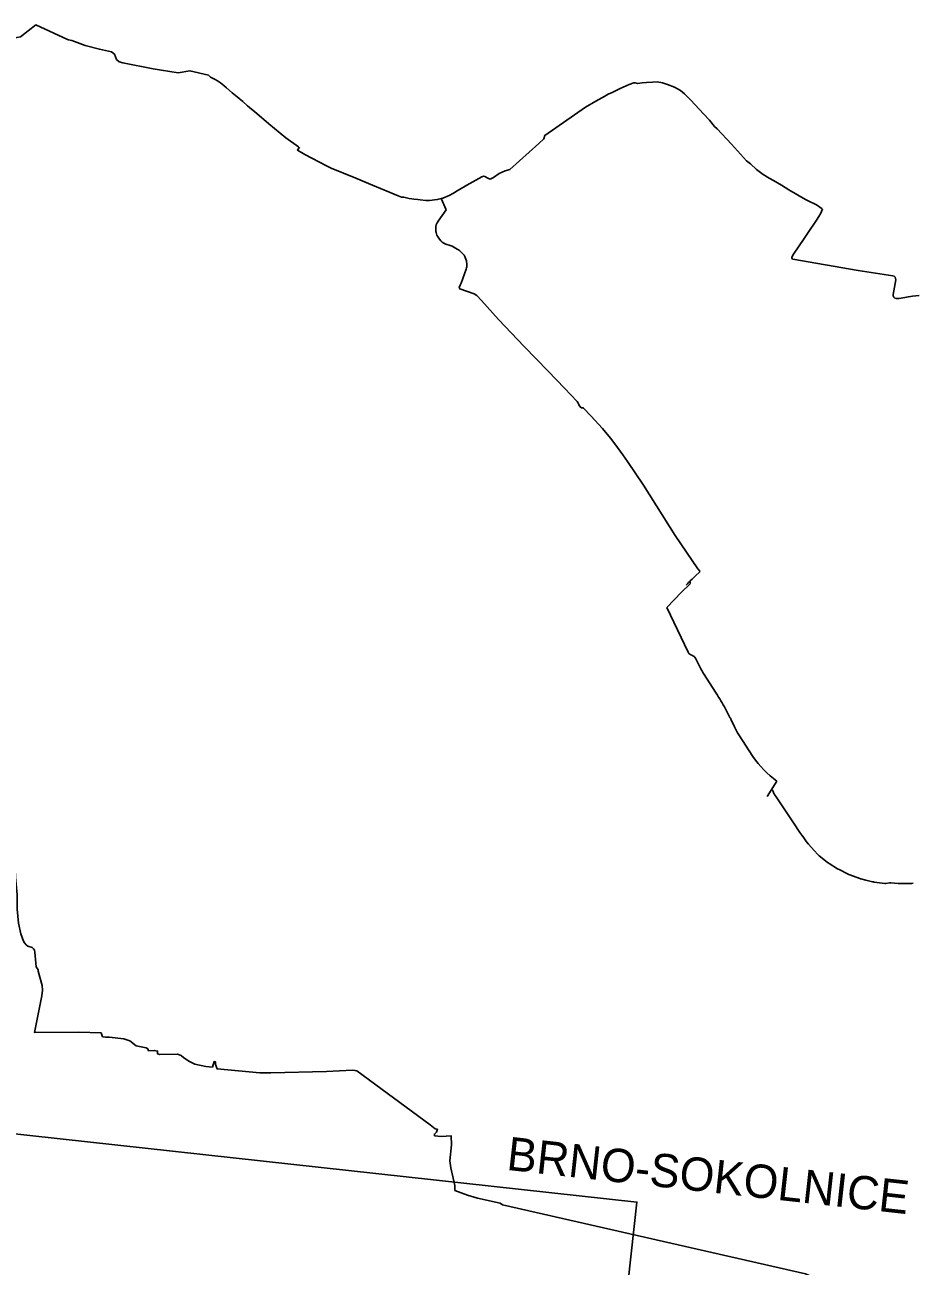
# Model space of a CAD drawing. Extents: x -678204 to -526855, y -1228851 to -1110393.
# Drawn here: x -596045 to -592047, y -1166903 to -1161319 of the extents above; entities that cross this region are included whole.
import ezdxf

# ---------------------------------------------------------------- set-up
doc = ezdxf.new("R2010")
doc.units = 0
for name, color, linetype in [('00_n_cyklo popisy ostatni', 7, 'Continuous'), ('00_n_cyklo provereni vedlejsi', 7, 'Continuous'), ('00_n_cyklo prujezdne podminecne rekreacni vedlejsi', 7, 'Continuous'), ('00_n_cyklo prujezdne rekreacni vedlejsi', 7, 'Continuous'), ('00_n_cyklo realizace rekreacni vedlejsi', 7, 'Continuous'), ('00_n_cyklo studie rekreacni vedlejsi', 7, 'Continuous'), ('00_n_cyklo trasovani rekreacni vedlejsi', 7, 'Continuous'), ('_HELP BIG', 7, 'Continuous')]:
    doc.layers.add(name, color=color, linetype=linetype)

msp = doc.modelspace()

# ---------------------------------------------------------------- linework, layer by layer
at = {"layer": '00_n_cyklo provereni vedlejsi'}
for p, q in [((-594063.9, -1162045.1), (-594055.8, -1162040.3)), ((-593007.5, -1163780.6), (-593026.2, -1163797.9)), ((-593053.4, -1163824.2), (-593051.1, -1163826.6)), ((-593050.2, -1163828.4), (-593050, -1163830.5))]:
    msp.add_line(p, q, dxfattribs=at)
for points in [[(-595994.8, -1161319.5), (-596063.8, -1161373.5), (-596097.6, -1161379.4), (-596197.5, -1161374), (-596330.9, -1161385.2)], [(-592456.3, -1162147.3), (-592482.8, -1162129.7), (-592519.5, -1162111.4), (-592532.2, -1162104.6), (-592606.1, -1162061.5), (-592639.6, -1162041.1), (-592675.4, -1162020.4), (-592695, -1162009.2), (-592722, -1161992.4), (-592752.3, -1161970.2), (-592779.3, -1161945.4), (-592797.4, -1161931), (-592864.9, -1161856), (-592929.3, -1161787.2), (-592940.6, -1161776.1), (-592963.2, -1161748.9), (-592991.1, -1161720.5), (-593048.4, -1161658.2), (-593076.4, -1161629.6), (-593094.6, -1161615.3), (-593121.4, -1161600.6), (-593153.5, -1161587.5), (-593175.4, -1161580.8), (-593199.7, -1161576.4), (-593219.6, -1161576.7), (-593247.8, -1161578.6), (-593266.2, -1161580.5), (-593288, -1161583.6)], [(-593441.7, -1161645.5), (-593435.4, -1161641), (-593419.5, -1161632), (-593401.3, -1161623.3), (-593365.4, -1161606.6), (-593325.4, -1161588.4), (-593304.6, -1161580.4), (-593298, -1161579.9), (-593288, -1161583.6)], [(-594055.8, -1162040.3), (-593987.5, -1162003.9), (-593981.1, -1162000.6), (-593974.3, -1162001.6), (-593958.9, -1162010.3), (-593950.5, -1162013.9), (-593935.3, -1162006.3), (-593910.1, -1161988.6), (-593882.5, -1161976.9), (-593862, -1161970.8), (-593731.7, -1161853.4), (-593708.8, -1161832.3), (-593704.2, -1161817), (-593521.4, -1161690.6), (-593476, -1161662.2), (-593435.4, -1161641)], [(-594099.4, -1162066), (-594115.3, -1162076.6), (-594134.5, -1162086.6), (-594164.4, -1162098.5), (-594171, -1162100.3)], [(-594099.4, -1162066), (-594063.9, -1162045.1)], [(-594364.4, -1162089.3), (-594349.9, -1162095), (-594344, -1162094.8), (-594338.7, -1162094.9), (-594326.8, -1162098), (-594314.5, -1162101), (-594303.1, -1162102.7), (-594294.3, -1162103.5), (-594276.8, -1162105.1), (-594265.6, -1162107.2), (-594240.5, -1162109.1)], [(-594171, -1162100.3), (-594189.1, -1162105.3), (-594223.1, -1162109.4), (-594240.5, -1162109.1)], [(-594149.4, -1162151.3), (-594170.9, -1162100.2)], [(-592593.2, -1162365.5), (-592590.6, -1162359.3), (-592585.7, -1162350.6), (-592560.5, -1162313.7), (-592541.1, -1162285.1), (-592522.7, -1162257.7), (-592482.7, -1162198.7), (-592471.6, -1162181.8), (-592461.7, -1162163.3), (-592455.6, -1162147.6)], [(-592588.7, -1162373.7), (-592294.7, -1162424.4), (-592138.6, -1162448.7)], [(-592126.1, -1162466), (-592137, -1162532.7)], [(-593005.2, -1163778.8), (-593016.6, -1163766.3), (-593118.8, -1163616.7), (-593260.7, -1163390.5), (-593332.9, -1163283.7), (-593354.5, -1163253.2), (-593390.5, -1163204.2), (-593409.6, -1163179.2), (-593445.8, -1163135.6), (-593497.8, -1163078.1), (-593531.1, -1163044.1), (-593534.3, -1163042.3), (-593537.1, -1163041.8), (-593540.6, -1163042.5), (-593550.9, -1163032.2), (-593552, -1163028), (-593554.2, -1163021.5), (-593559.4, -1163014.6), (-593616.3, -1162953.6), (-593690.3, -1162877.3), (-593797.3, -1162766), (-593912.9, -1162644.5), (-593989.9, -1162559.1), (-594010.6, -1162537.5), (-594023.4, -1162530), (-594087.2, -1162506.6), (-594089.6, -1162501.7), (-594085.2, -1162490.6), (-594081.1, -1162481)], [(-592123.2, -1162550.1), (-592114.2, -1162550.6)], [(-593051.3, -1163834.3), (-593089.4, -1163870.9), (-593156.3, -1163940.6)]]:
    msp.add_lwpolyline(points, dxfattribs=at)
for centre, radius, start, end in [((-592587.6, -1162367.8), 6, 157.2978, 260.2148), ((-592140.9, -1162463.6), 15, 350.7572, 81.145), ((-592122.2, -1162535.1), 15, 170.7572, 266.267), ((-592113.2, -1162535.7), 15, 266.267, 280.5096), ((-592347, -1164529.2), 998, 132.8816, 136.2737), ((-593054.4, -1163831), 4.5, 313.8822, 6.511), ((-593053.2, -1163828.7), 3, 6.511, 45.0583)]:
    msp.add_arc(centre, radius, start, end, dxfattribs=at)
at = {"layer": '00_n_cyklo prujezdne podminecne rekreacni vedlejsi'}
for points in [[(-595847.9, -1161386.6), (-595852.1, -1161385), (-595994.8, -1161319.5)], [(-594364.4, -1162089.3), (-594479.4, -1162040.8), (-594555.3, -1162008.9), (-594665.9, -1161964.9), (-594686.9, -1161954.1), (-594785.3, -1161902.7), (-594818.2, -1161882.6), (-594809.1, -1161870.1)]]:
    msp.add_lwpolyline(points, dxfattribs=at)
at = {"layer": '00_n_cyklo prujezdne rekreacni vedlejsi'}
for p, q in [((-593156.3, -1163940.6), (-593059.9, -1164142)), ((-593026.7, -1164168.6), (-593005.9, -1164210.1)), ((-592990.5, -1164237.1), (-592933.7, -1164325.7)), ((-592873.2, -1164432.5), (-592892, -1164397)), ((-592866.7, -1164445.5), (-592852, -1164476.9)), ((-592832, -1164512.7), (-592768.1, -1164611))]:
    msp.add_line(p, q, dxfattribs=at)
for points in [[(-595218.8, -1161546.6), (-595301.4, -1161526.2), (-595354.8, -1161534.7), (-595466.5, -1161518.1), (-595603, -1161490.7), (-595620.3, -1161486.7), (-595631.6, -1161474.8), (-595640.8, -1161451.6), (-595655.2, -1161441.2), (-595708.8, -1161429), (-595772.4, -1161413.2), (-595832.8, -1161389.7), (-595847.9, -1161386.6)], [(-595218.8, -1161546.6), (-595209, -1161555.4), (-595188.5, -1161565.9), (-595177.3, -1161572.1), (-595163.8, -1161581.1), (-595149.8, -1161591.8), (-595137.5, -1161602.7), (-595111.2, -1161625), (-595088.5, -1161644), (-595063.7, -1161664.5), (-595042.3, -1161683.2), (-595024.4, -1161698.2), (-595011.6, -1161709.3), (-594946.8, -1161764.7), (-594895.6, -1161807.5), (-594870.8, -1161827.3), (-594812.9, -1161867.8)], [(-594185, -1162203.4), (-594149.4, -1162151.3)], [(-594194.5, -1162248.5), (-594195.8, -1162235.4)], [(-594178.5, -1162284.1), (-594187.2, -1162270)], [(-594130.8, -1162311.5), (-594150.5, -1162305.6)], [(-594098.6, -1162328.2), (-594121, -1162315.7)], [(-594076, -1162346.9), (-594089.4, -1162334.8)], [(-594056.1, -1162397.4), (-594057.2, -1162381.6), (-594062.6, -1162366.8)], [(-594081.1, -1162481), (-594058.9, -1162418)]]:
    msp.add_lwpolyline(points, dxfattribs=at)
for centre, radius, start, end in [((-594146, -1162234.3), 49.8, 141.6362, 181.2596), ((-594144.7, -1162243.7), 50, 185.5177, 211.7691), ((-594136, -1162257.7), 50, 211.7691, 253.167), ((-594145.3, -1162359.4), 50, 60.8479, 73.167), ((-594123, -1162371.9), 50, 47.8163, 60.8479), ((-594109.6, -1162384), 50, 20.0691, 47.8163), ((-594105.9, -1162401), 50, 340.1824, 4.2163), ((-593037.3, -1164131.2), 25, 205.5744, 256.4254), ((-593049.1, -1164179.8), 25, 26.6439, 76.4254), ((-592740.7, -1164077), 296.8, 206.6439, 212.6625), ((-593778.3, -1164867.2), 1003.2, 27.9453, 32.6625), ((-593141.1, -1164574.6), 303.2, 25.1958, 27.9453), ((-592580.5, -1164349.1), 300, 205.1958, 213.0379), ((-592362.1, -1164326.2), 495.9, 215.0389, 232.9046)]:
    msp.add_arc(centre, radius, start, end, dxfattribs=at)
at = {"layer": '00_n_cyklo realizace rekreacni vedlejsi'}
for p, q in [((-592661.2, -1164721.8), (-592704.8, -1164790.4)), ((-592684.5, -1164757.2), (-592680.9, -1164761.6)), ((-592676.8, -1164768.5), (-592673.7, -1164776.5)), ((-592092.5, -1165182.7), (-592058.6, -1165181.9))]:
    msp.add_line(p, q, dxfattribs=at)
for points in [[(-592671.3, -1164781.1), (-592670.7, -1164782), (-592660.9, -1164796.7), (-592630.7, -1164842), (-592606.8, -1164877.8), (-592585.7, -1164909.3), (-592557.1, -1164952), (-592548.9, -1164964.1), (-592543, -1164972.3), (-592526.9, -1164994), (-592518.2, -1165005.4), (-592493.2, -1165033.2), (-592476.3, -1165051.8)], [(-592470.3, -1165057.4), (-592441.5, -1165080.3), (-592433.2, -1165086.9)], [(-592425.8, -1165092.1), (-592387.7, -1165115.9)], [(-592380.6, -1165119.8), (-592340.1, -1165139.7)], [(-592332.7, -1165142.9), (-592287.8, -1165159.4)], [(-592282.8, -1165161), (-592261, -1165166.6), (-592229.7, -1165174.5)], [(-592223.5, -1165175.6), (-592175.5, -1165181.5)], [(-592170.4, -1165181.5), (-592154.3, -1165179.3)], [(-592147.7, -1165179.2), (-592114.4, -1165182)]]:
    msp.add_lwpolyline(points, dxfattribs=at)
for centre, radius, start, end in [((-592700.1, -1164777.7), 25, 21.3516, 39.8752), ((-592650.4, -1164767.3), 25, 201.3516, 213.3063), ((-592439.3, -1165018.3), 50, 222.2154, 231.6118), ((-592383.5, -1165024.2), 80, 231.6152, 238.0345), ((-592345.3, -1165048), 80, 238.0345, 243.8749), ((-592304.9, -1165067.8), 80, 243.8749, 249.6901), ((-592270.5, -1165112.6), 50, 249.6901, 255.7715), ((-592217.4, -1165126), 50, 255.7906, 262.9748), ((-592173.1, -1165161.7), 20, 262.9748, 277.75), ((-592150.3, -1165209), 30, 85.0972, 97.75), ((-592097.3, -1164982.7), 200, 265.0972, 271.3805), ((-592061, -1165081.9), 100, 271.3805, 277.8459)]:
    msp.add_arc(centre, radius, start, end, dxfattribs=at)
at = {"layer": '00_n_cyklo studie rekreacni vedlejsi'}
for points in [[(-592110.4, -1162550.4), (-592068.5, -1162542.6), (-592050.3, -1162539.9)], [(-592050.3, -1162539.9), (-592020.6, -1162537.6)], [(-595985, -1165570.7), (-595994.2, -1165556.9), (-595998.8, -1165491.6), (-596001, -1165482.5), (-596005.6, -1165475.4), (-596012.1, -1165470.7), (-596030.9, -1165463.6), (-596039, -1165457.6), (-596046.4, -1165449.5), (-596050.5, -1165440.8), (-596063, -1165408.6), (-596072.8, -1165361), (-596079, -1165298.1), (-596079.6, -1165233), (-596086.6, -1165152.9), (-596087.6, -1165118.8)], [(-595700.5, -1165854.1), (-595801.3, -1165851), (-596001.5, -1165852), (-595968.2, -1165688.1), (-595965, -1165661.7), (-595966.9, -1165640.4), (-595985.2, -1165576.5), (-595985, -1165570.7)], [(-595487.5, -1165935.4), (-595491.2, -1165925.8), (-595498.7, -1165921.4), (-595543.3, -1165913), (-595572.3, -1165889.5), (-595598.6, -1165881.2), (-595664.3, -1165874), (-595681, -1165874), (-595694.8, -1165871.4), (-595700.5, -1165854.1)], [(-595302.9, -1165983.5), (-595328.6, -1165966), (-595340.6, -1165955.3), (-595357.7, -1165949.9), (-595437.1, -1165951.3), (-595447.1, -1165948.8), (-595447.4, -1165935.7), (-595462.2, -1165932.6), (-595487.5, -1165935.4)], [(-595199.4, -1166008.9), (-595230.5, -1166004.9), (-595278.9, -1165995.2), (-595302.9, -1165983.5)], [(-594686.4, -1166027.1), (-594938.3, -1166033.9), (-594987.6, -1166034.2), (-595179.2, -1166016.1), (-595186.2, -1165995.7), (-595187.3, -1165984), (-595192.6, -1165983.5), (-595199.4, -1166008.9)], [(-594200.7, -1166317.5), (-594201.4, -1166309.4), (-594192.1, -1166300.2), (-594187.7, -1166287.4), (-594198.3, -1166286.1), (-594221.1, -1166267.7), (-594550.7, -1166025.5), (-594558.9, -1166022.6), (-594570.5, -1166021.1), (-594686.4, -1166027.1)], [(-594110.3, -1166563.2), (-594109.7, -1166541.1), (-594127.7, -1166461), (-594132.8, -1166429.5), (-594125.4, -1166357.9), (-594126.5, -1166316.7), (-594171.5, -1166320.2), (-594200.7, -1166317.5)], [(-592237.9, -1167314.7), (-592286.2, -1167247.9), (-592294.6, -1167240.5), (-592488.4, -1166972.1), (-592500.1, -1166958.2), (-592514.9, -1166946), (-592531.9, -1166938.4), (-593895.3, -1166627.3), (-593905.3, -1166619.8), (-594008.1, -1166597), (-594053.4, -1166583.7), (-594110.3, -1166563.2)]]:
    msp.add_lwpolyline(points, dxfattribs=at)
at = {"layer": '00_n_cyklo trasovani rekreacni vedlejsi'}
for p, q in [((-594063.9, -1162045.1), (-594055.8, -1162040.3)), ((-593007.5, -1163780.6), (-593026.2, -1163797.9)), ((-593053.4, -1163824.2), (-593051.1, -1163826.6)), ((-593050.2, -1163828.4), (-593050, -1163830.5)), ((-593156.3, -1163940.6), (-593059.9, -1164142)), ((-593026.7, -1164168.6), (-593005.9, -1164210.1)), ((-592990.5, -1164237.1), (-592933.7, -1164325.7)), ((-592873.2, -1164432.5), (-592892, -1164397)), ((-592866.7, -1164445.5), (-592852, -1164476.9)), ((-592832, -1164512.7), (-592768.1, -1164611)), ((-592661.2, -1164721.8), (-592704.8, -1164790.4)), ((-592684.5, -1164757.2), (-592680.9, -1164761.6)), ((-592676.8, -1164768.5), (-592673.7, -1164776.5)), ((-592092.5, -1165182.7), (-592058.6, -1165181.9))]:
    msp.add_line(p, q, dxfattribs=at)
for points in [[(-595994.8, -1161319.5), (-596063.8, -1161373.5), (-596097.6, -1161379.4), (-596197.5, -1161374), (-596330.9, -1161385.2)], [(-595847.9, -1161386.6), (-595852.1, -1161385), (-595994.8, -1161319.5)], [(-595218.8, -1161546.6), (-595301.4, -1161526.2), (-595354.8, -1161534.7), (-595466.5, -1161518.1), (-595603, -1161490.7), (-595620.3, -1161486.7), (-595631.6, -1161474.8), (-595640.8, -1161451.6), (-595655.2, -1161441.2), (-595708.8, -1161429), (-595772.4, -1161413.2), (-595832.8, -1161389.7), (-595847.9, -1161386.6)], [(-595218.8, -1161546.6), (-595209, -1161555.4), (-595188.5, -1161565.9), (-595177.3, -1161572.1), (-595163.8, -1161581.1), (-595149.8, -1161591.8), (-595137.5, -1161602.7), (-595111.2, -1161625), (-595088.5, -1161644), (-595063.7, -1161664.5), (-595042.3, -1161683.2), (-595024.4, -1161698.2), (-595011.6, -1161709.3), (-594946.8, -1161764.7), (-594895.6, -1161807.5), (-594870.8, -1161827.3), (-594812.9, -1161867.8)], [(-592456.3, -1162147.3), (-592482.8, -1162129.7), (-592519.5, -1162111.4), (-592532.2, -1162104.6), (-592606.1, -1162061.5), (-592639.6, -1162041.1), (-592675.4, -1162020.4), (-592695, -1162009.2), (-592722, -1161992.4), (-592752.3, -1161970.2), (-592779.3, -1161945.4), (-592797.4, -1161931), (-592864.9, -1161856), (-592929.3, -1161787.2), (-592940.6, -1161776.1), (-592963.2, -1161748.9), (-592991.1, -1161720.5), (-593048.4, -1161658.2), (-593076.4, -1161629.6), (-593094.6, -1161615.3), (-593121.4, -1161600.6), (-593153.5, -1161587.5), (-593175.4, -1161580.8), (-593199.7, -1161576.4), (-593219.6, -1161576.7), (-593247.8, -1161578.6), (-593266.2, -1161580.5), (-593288, -1161583.6)], [(-593441.7, -1161645.5), (-593435.4, -1161641), (-593419.5, -1161632), (-593401.3, -1161623.3), (-593365.4, -1161606.6), (-593325.4, -1161588.4), (-593304.6, -1161580.4), (-593298, -1161579.9), (-593288, -1161583.6)], [(-594055.8, -1162040.3), (-593987.5, -1162003.9), (-593981.1, -1162000.6), (-593974.3, -1162001.6), (-593958.9, -1162010.3), (-593950.5, -1162013.9), (-593935.3, -1162006.3), (-593910.1, -1161988.6), (-593882.5, -1161976.9), (-593862, -1161970.8), (-593731.7, -1161853.4), (-593708.8, -1161832.3), (-593704.2, -1161817), (-593521.4, -1161690.6), (-593476, -1161662.2), (-593435.4, -1161641)], [(-594364.4, -1162089.3), (-594479.4, -1162040.8), (-594555.3, -1162008.9), (-594665.9, -1161964.9), (-594686.9, -1161954.1), (-594785.3, -1161902.7), (-594818.2, -1161882.6), (-594809.1, -1161870.1)], [(-594099.4, -1162066), (-594115.3, -1162076.6), (-594134.5, -1162086.6), (-594164.4, -1162098.5), (-594171, -1162100.3)], [(-594099.4, -1162066), (-594063.9, -1162045.1)], [(-594364.4, -1162089.3), (-594349.9, -1162095), (-594344, -1162094.8), (-594338.7, -1162094.9), (-594326.8, -1162098), (-594314.5, -1162101), (-594303.1, -1162102.7), (-594294.3, -1162103.5), (-594276.8, -1162105.1), (-594265.6, -1162107.2), (-594240.5, -1162109.1)], [(-594171, -1162100.3), (-594189.1, -1162105.3), (-594223.1, -1162109.4), (-594240.5, -1162109.1)], [(-594149.4, -1162151.3), (-594170.9, -1162100.2)], [(-594185, -1162203.4), (-594149.4, -1162151.3)], [(-592593.2, -1162365.5), (-592590.6, -1162359.3), (-592585.7, -1162350.6), (-592560.5, -1162313.7), (-592541.1, -1162285.1), (-592522.7, -1162257.7), (-592482.7, -1162198.7), (-592471.6, -1162181.8), (-592461.7, -1162163.3), (-592455.6, -1162147.6)], [(-594194.5, -1162248.5), (-594195.8, -1162235.4)], [(-594178.5, -1162284.1), (-594187.2, -1162270)], [(-594130.8, -1162311.5), (-594150.5, -1162305.6)], [(-594098.6, -1162328.2), (-594121, -1162315.7)], [(-594076, -1162346.9), (-594089.4, -1162334.8)], [(-594056.1, -1162397.4), (-594057.2, -1162381.6), (-594062.6, -1162366.8)], [(-592588.7, -1162373.7), (-592294.7, -1162424.4), (-592138.6, -1162448.7)], [(-594081.1, -1162481), (-594058.9, -1162418)], [(-592126.1, -1162466), (-592137, -1162532.7)], [(-593005.2, -1163778.8), (-593016.6, -1163766.3), (-593118.8, -1163616.7), (-593260.7, -1163390.5), (-593332.9, -1163283.7), (-593354.5, -1163253.2), (-593390.5, -1163204.2), (-593409.6, -1163179.2), (-593445.8, -1163135.6), (-593497.8, -1163078.1), (-593531.1, -1163044.1), (-593534.3, -1163042.3), (-593537.1, -1163041.8), (-593540.6, -1163042.5), (-593550.9, -1163032.2), (-593552, -1163028), (-593554.2, -1163021.5), (-593559.4, -1163014.6), (-593616.3, -1162953.6), (-593690.3, -1162877.3), (-593797.3, -1162766), (-593912.9, -1162644.5), (-593989.9, -1162559.1), (-594010.6, -1162537.5), (-594023.4, -1162530), (-594087.2, -1162506.6), (-594089.6, -1162501.7), (-594085.2, -1162490.6), (-594081.1, -1162481)], [(-592123.2, -1162550.1), (-592114.2, -1162550.6)], [(-592110.4, -1162550.4), (-592068.5, -1162542.6), (-592050.3, -1162539.9)], [(-592050.3, -1162539.9), (-592020.6, -1162537.6)], [(-593051.3, -1163834.3), (-593089.4, -1163870.9), (-593156.3, -1163940.6)], [(-592671.3, -1164781.1), (-592670.7, -1164782), (-592660.9, -1164796.7), (-592630.7, -1164842), (-592606.8, -1164877.8), (-592585.7, -1164909.3), (-592557.1, -1164952), (-592548.9, -1164964.1), (-592543, -1164972.3), (-592526.9, -1164994), (-592518.2, -1165005.4), (-592493.2, -1165033.2), (-592476.3, -1165051.8)], [(-592470.3, -1165057.4), (-592441.5, -1165080.3), (-592433.2, -1165086.9)], [(-592425.8, -1165092.1), (-592387.7, -1165115.9)], [(-595985, -1165570.7), (-595994.2, -1165556.9), (-595998.8, -1165491.6), (-596001, -1165482.5), (-596005.6, -1165475.4), (-596012.1, -1165470.7), (-596030.9, -1165463.6), (-596039, -1165457.6), (-596046.4, -1165449.5), (-596050.5, -1165440.8), (-596063, -1165408.6), (-596072.8, -1165361), (-596079, -1165298.1), (-596079.6, -1165233), (-596086.6, -1165152.9), (-596087.6, -1165118.8)], [(-592380.6, -1165119.8), (-592340.1, -1165139.7)], [(-592332.7, -1165142.9), (-592287.8, -1165159.4)], [(-592282.8, -1165161), (-592261, -1165166.6), (-592229.7, -1165174.5)], [(-592223.5, -1165175.6), (-592175.5, -1165181.5)], [(-592170.4, -1165181.5), (-592154.3, -1165179.3)], [(-592147.7, -1165179.2), (-592114.4, -1165182)], [(-595700.5, -1165854.1), (-595801.3, -1165851), (-596001.5, -1165852), (-595968.2, -1165688.1), (-595965, -1165661.7), (-595966.9, -1165640.4), (-595985.2, -1165576.5), (-595985, -1165570.7)], [(-595487.5, -1165935.4), (-595491.2, -1165925.8), (-595498.7, -1165921.4), (-595543.3, -1165913), (-595572.3, -1165889.5), (-595598.6, -1165881.2), (-595664.3, -1165874), (-595681, -1165874), (-595694.8, -1165871.4), (-595700.5, -1165854.1)], [(-595302.9, -1165983.5), (-595328.6, -1165966), (-595340.6, -1165955.3), (-595357.7, -1165949.9), (-595437.1, -1165951.3), (-595447.1, -1165948.8), (-595447.4, -1165935.7), (-595462.2, -1165932.6), (-595487.5, -1165935.4)], [(-595199.4, -1166008.9), (-595230.5, -1166004.9), (-595278.9, -1165995.2), (-595302.9, -1165983.5)], [(-594686.4, -1166027.1), (-594938.3, -1166033.9), (-594987.6, -1166034.2), (-595179.2, -1166016.1), (-595186.2, -1165995.7), (-595187.3, -1165984), (-595192.6, -1165983.5), (-595199.4, -1166008.9)], [(-594200.7, -1166317.5), (-594201.4, -1166309.4), (-594192.1, -1166300.2), (-594187.7, -1166287.4), (-594198.3, -1166286.1), (-594221.1, -1166267.7), (-594550.7, -1166025.5), (-594558.9, -1166022.6), (-594570.5, -1166021.1), (-594686.4, -1166027.1)], [(-594110.3, -1166563.2), (-594109.7, -1166541.1), (-594127.7, -1166461), (-594132.8, -1166429.5), (-594125.4, -1166357.9), (-594126.5, -1166316.7), (-594171.5, -1166320.2), (-594200.7, -1166317.5)], [(-592237.9, -1167314.7), (-592286.2, -1167247.9), (-592294.6, -1167240.5), (-592488.4, -1166972.1), (-592500.1, -1166958.2), (-592514.9, -1166946), (-592531.9, -1166938.4), (-593895.3, -1166627.3), (-593905.3, -1166619.8), (-594008.1, -1166597), (-594053.4, -1166583.7), (-594110.3, -1166563.2)]]:
    msp.add_lwpolyline(points, dxfattribs=at)
for centre, radius, start, end in [((-594146, -1162234.3), 49.8, 141.6362, 181.2596), ((-594144.7, -1162243.7), 50, 185.5177, 211.7691), ((-594136, -1162257.7), 50, 211.7691, 253.167), ((-594145.3, -1162359.4), 50, 60.8479, 73.167), ((-594123, -1162371.9), 50, 47.8163, 60.8479), ((-594109.6, -1162384), 50, 20.0691, 47.8163), ((-594105.9, -1162401), 50, 340.1824, 4.2163), ((-592587.6, -1162367.8), 6, 157.2978, 260.2148), ((-592140.9, -1162463.6), 15, 350.7572, 81.145), ((-592122.2, -1162535.1), 15, 170.7572, 266.267), ((-592113.2, -1162535.7), 15, 266.267, 280.5096), ((-592347, -1164529.2), 998, 132.8816, 136.2737), ((-593054.4, -1163831), 4.5, 313.8822, 6.511), ((-593053.2, -1163828.7), 3, 6.511, 45.0583), ((-593037.3, -1164131.2), 25, 205.5744, 256.4254), ((-593049.1, -1164179.8), 25, 26.6439, 76.4254), ((-592740.7, -1164077), 296.8, 206.6439, 212.6625), ((-593778.3, -1164867.2), 1003.2, 27.9453, 32.6625), ((-593141.1, -1164574.6), 303.2, 25.1958, 27.9453), ((-592580.5, -1164349.1), 300, 205.1958, 213.0379), ((-592362.1, -1164326.2), 495.9, 215.0389, 232.9046), ((-592700.1, -1164777.7), 25, 21.3516, 39.8752), ((-592650.4, -1164767.3), 25, 201.3516, 213.3063), ((-592439.3, -1165018.3), 50, 222.2154, 231.6118), ((-592383.5, -1165024.2), 80, 231.6152, 238.0345), ((-592345.3, -1165048), 80, 238.0345, 243.8749), ((-592304.9, -1165067.8), 80, 243.8749, 249.6901), ((-592270.5, -1165112.6), 50, 249.6901, 255.7715), ((-592217.4, -1165126), 50, 255.7906, 262.9748), ((-592173.1, -1165161.7), 20, 262.9748, 277.75), ((-592150.3, -1165209), 30, 85.0972, 97.75), ((-592097.3, -1164982.7), 200, 265.0972, 271.3805), ((-592061, -1165081.9), 100, 271.3805, 277.8459)]:
    msp.add_arc(centre, radius, start, end, dxfattribs=at)
at = {"layer": '_HELP BIG'}
msp.add_lwpolyline([(-616541.9, -1192690.5), (-613435.7, -1164403.2), (-593290.7, -1166615.3), (-596396.9, -1194902.6)], close=True, dxfattribs=at)

# ---------------------------------------------------------------- texts
at = {"layer": '00_n_cyklo popisy ostatni'}
msp.add_text('BRNO-SOKOLNICE', height=150, rotation=353.6836, dxfattribs=at).set_placement((-593880.5, -1166469.8))

doc.saveas('drawing.dxf')
